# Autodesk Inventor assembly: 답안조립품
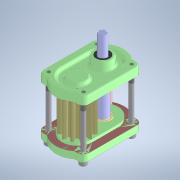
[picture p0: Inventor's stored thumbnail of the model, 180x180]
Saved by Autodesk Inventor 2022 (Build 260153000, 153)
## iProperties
Created: 2023-06
Part Number: 답안조립품
Document SubType Name: Assembly
Designer: PC-01
Author: PC-01
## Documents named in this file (12)
- C:\Users\PC-01\Desktop\새 폴더\답안조립품.iam
- C:\Users\PC-01\Desktop\새 폴더\본체.ipt
- C:\Users\PC-01\Desktop\새 폴더\가스켓.ipt
- C:\Users\PC-01\Desktop\새 폴더\뒷커버.ipt
- C:\Users\PC-01\Desktop\새 폴더\니들베어링 NA 4902.ipt
- C:\Users\PC-01\Desktop\새 폴더\샤프트.ipt
- C:\Users\PC-01\Desktop\새 폴더\묻힘키 6x6x40.ipt
- C:\Users\PC-01\Desktop\새 폴더\메인 드라이브 기어.ipt
- C:\Users\PC-01\Desktop\새 폴더\서브 드라이브 기어.ipt
- C:\Users\PC-01\Desktop\새 폴더\앞커버.ipt
- C:\Users\PC-01\Desktop\새 폴더\오일실 15 25 7.ipt
- C:\Users\PC-01\Desktop\새 폴더\육각 소켓 머리 볼트 M8 x 100.ipt
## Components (2 placed, 1 different names)
1. 가스켓:1
2. 가스켓:2
